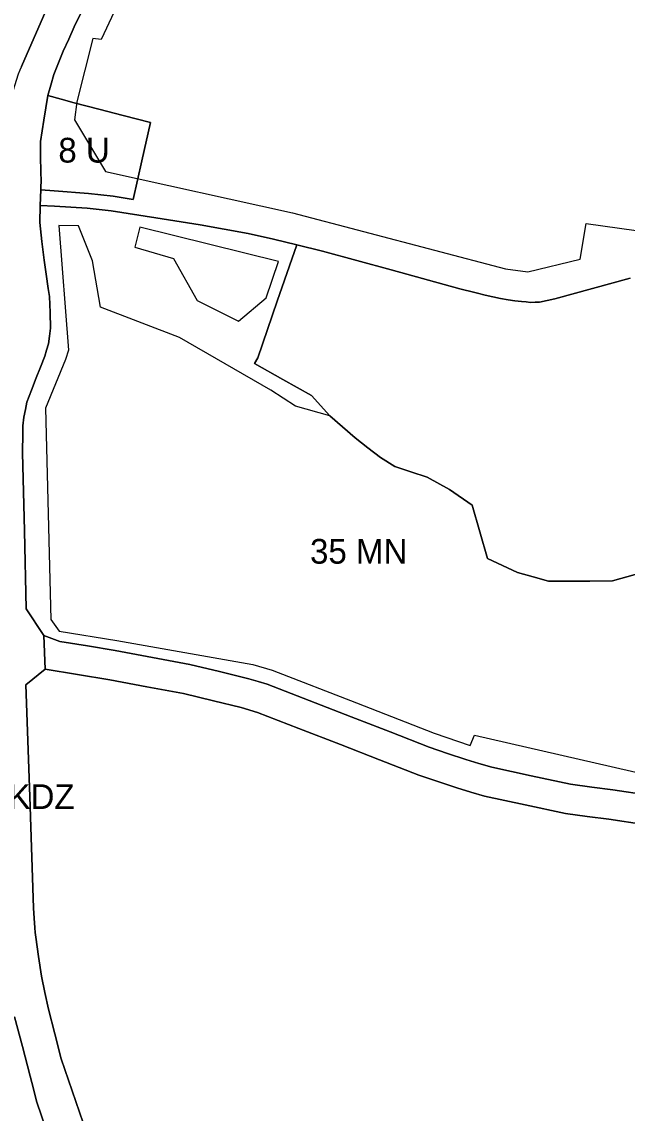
# Model space of a CAD drawing. Extents: x -294445 to -292055, y 21869 to 23693.
# Drawn here: x -293575 to -293330.1, y 22598.3 to 23039.5 of the extents above; entities that cross this region are included whole.
import ezdxf

# ---------------------------------------------------------------- set-up
doc = ezdxf.new("R2010")
doc.units = 0
for name, color, linetype in [('linie_rozgraniczajace', 7, 'Continuous'), ('linie_zabudowy_nieprzekraczalne', 7, 'Continuous'), ('oznaczenia_przeznaczen', 7, 'Continuous')]:
    doc.layers.add(name, color=color, linetype=linetype)

msp = doc.modelspace()

# ---------------------------------------------------------------- linework, layer by layer
at = {"layer": 'linie_rozgraniczajace'}
for points in [[(-293598.18, 23056.18), (-293594.8, 23074.713), (-293589.79, 23085.71), (-293551.776, 23075.056), (-293563.422, 23048.255), (-293575.068, 23021.454), (-293575.727, 23019.979), (-293576.434, 23018.253), (-293578.598, 23011.442), (-293580.762, 23004.631), (-293592.68, 23009.07)], [(-293567.426, 22991.126), (-293566.733, 22995.416), (-293566.039, 22999.706), (-293565.226, 23004.706), (-293564.413, 23009.705), (-293559.112, 23008.208), (-293553.81, 23006.71), (-293543.87, 23004.15), (-293533.93, 23001.59), (-293522.927, 22998.822), (-293526.415, 22983.261), (-293529.902, 22967.7), (-293538.002, 22968.955), (-293548.059, 22970.061), (-293561.867, 22971.094), (-293567.276, 22971.479), (-293567.12, 22976.301), (-293567.209, 22977.594), (-293567.298, 22978.886), (-293567.362, 22985.006)]]:
    msp.add_lwpolyline(points, close=True, dxfattribs=at)
for points in [[(-293575.068, 23021.454), (-293563.422, 23048.255)], [(-293551.136, 23042.939), (-293553.755, 23037.405), (-293555.994, 23032.499), (-293558.234, 23027.592), (-293560.101, 23022.855), (-293561.968, 23018.117), (-293563.19, 23013.911), (-293564.413, 23009.705), (-293565.226, 23004.706), (-293566.039, 22999.706), (-293566.733, 22995.416), (-293567.426, 22991.126), (-293567.362, 22985.006), (-293567.298, 22978.886), (-293567.209, 22977.594), (-293567.12, 22976.301), (-293567.276, 22971.479), (-293567.476, 22965.273), (-293567.702, 22958.276), (-293566.811, 22950.599), (-293565.94, 22943.17), (-293565.102, 22937.409), (-293564.264, 22931.648), (-293563.793, 22928.413), (-293563.556, 22921.992), (-293563.32, 22915.571), (-293563.761, 22912.432), (-293564.202, 22909.293), (-293564.946, 22906.779), (-293565.69, 22904.265), (-293567.391, 22899.898), (-293569.093, 22895.532), (-293570.995, 22890.613), (-293572.898, 22885.695), (-293573.505, 22882.748), (-293574.135, 22879.675), (-293574.614, 22876.19), (-293574.596, 22873.354), (-293574.578, 22870.518), (-293574.621, 22867.876), (-293574.664, 22865.234), (-293573.943, 22833.709), (-293573.222, 22802.185), (-293566.058, 22791.341), (-293565.492, 22777.838), (-293573.29, 22771.4), (-293571.766, 22726.259), (-293570.243, 22681.117), (-293569.983, 22677.189), (-293569.723, 22673.26), (-293569.542, 22671.35), (-293569.36, 22669.44), (-293568.156, 22661.578), (-293566.952, 22653.716), (-293565.59, 22647.051), (-293564.229, 22640.385), (-293561.607, 22630.327), (-293558.985, 22620.268), (-293548.673, 22590.091)], [(-293567.476, 22965.273), (-293567.276, 22971.479), (-293561.867, 22971.094), (-293548.059, 22970.061), (-293538.002, 22968.955), (-293529.902, 22967.7), (-293526.415, 22983.261), (-293522.927, 22998.822), (-293533.93, 23001.59), (-293543.87, 23004.15), (-293553.81, 23006.71), (-293559.112, 23008.208), (-293564.413, 23009.705), (-293563.19, 23013.911), (-293561.968, 23018.117), (-293560.101, 23022.855), (-293558.234, 23027.592), (-293555.994, 23032.499), (-293553.755, 23037.405), (-293551.136, 23042.939)], [(-293574.664, 22865.234), (-293574.621, 22867.876), (-293574.578, 22870.518), (-293574.596, 22873.354), (-293574.614, 22876.19), (-293574.135, 22879.675), (-293573.505, 22882.748), (-293572.898, 22885.695), (-293570.995, 22890.613), (-293569.093, 22895.532), (-293567.391, 22899.898), (-293565.69, 22904.265), (-293564.946, 22906.779), (-293564.202, 22909.293), (-293563.761, 22912.432), (-293563.32, 22915.571), (-293563.556, 22921.992), (-293563.793, 22928.413), (-293564.264, 22931.648), (-293565.102, 22937.409), (-293565.94, 22943.17), (-293566.811, 22950.599), (-293567.702, 22958.276), (-293567.476, 22965.273), (-293561.684, 22964.9), (-293548.576, 22964.082), (-293538.789, 22963.005), (-293520.8, 22960.218), (-293502.81, 22957.43), (-293483.37, 22953.85), (-293473.13, 22951.647), (-293463.772, 22949.32), (-293471.671, 22926.48), (-293479.57, 22903.64), (-293480.89, 22901.32), (-293469.335, 22894.84), (-293457.778, 22888.362), (-293450.38, 22880.16), (-293445.23, 22875.71), (-293440.08, 22871.26), (-293435.01, 22867.315), (-293429.94, 22863.37), (-293424.05, 22859.76), (-293417.565, 22857.56), (-293411.08, 22855.36), (-293401.95, 22850.45), (-293392.8, 22844.05), (-293386.57, 22822.54), (-293380.53, 22819.69), (-293374.49, 22816.84), (-293368.21, 22815.11), (-293361.93, 22813.38), (-293353.545, 22813.4), (-293345.16, 22813.42), (-293336.05, 22813.51), (-293326.93, 22816.11)], [(-293328.905, 22935.847), (-293344.144, 22931.667), (-293359.383, 22927.487), (-293362.471, 22926.836), (-293365.559, 22926.185), (-293367.365, 22926.105), (-293369.171, 22926.025), (-293370.996, 22926.225), (-293372.822, 22926.425), (-293375.557, 22926.734), (-293378.292, 22927.044), (-293381.345, 22927.647), (-293384.398, 22928.249), (-293387.536, 22929.005), (-293390.675, 22929.761), (-293393.404, 22930.442), (-293396.133, 22931.124), (-293397.784, 22931.56), (-293425.592, 22939.15), (-293453.399, 22946.741), (-293463.772, 22949.32), (-293473.13, 22951.647), (-293483.37, 22953.85), (-293502.81, 22957.43), (-293520.8, 22960.218), (-293538.789, 22963.005), (-293548.576, 22964.082), (-293561.684, 22964.9), (-293567.476, 22965.273)], [(-293326.93, 22816.11), (-293336.05, 22813.51), (-293345.16, 22813.42), (-293353.545, 22813.4), (-293361.93, 22813.38), (-293368.21, 22815.11), (-293374.49, 22816.84), (-293380.53, 22819.69), (-293386.57, 22822.54), (-293392.8, 22844.05), (-293401.95, 22850.45), (-293411.08, 22855.36), (-293417.565, 22857.56), (-293424.05, 22859.76), (-293429.94, 22863.37), (-293435.01, 22867.315), (-293440.08, 22871.26), (-293445.23, 22875.71), (-293450.38, 22880.16), (-293457.778, 22888.362), (-293469.335, 22894.84), (-293480.89, 22901.32), (-293479.57, 22903.64), (-293471.671, 22926.48), (-293463.772, 22949.32), (-293453.399, 22946.741), (-293425.592, 22939.15), (-293397.784, 22931.56), (-293396.133, 22931.124), (-293393.404, 22930.442), (-293390.675, 22929.761), (-293387.536, 22929.005), (-293384.398, 22928.249), (-293381.345, 22927.647), (-293378.292, 22927.044), (-293375.557, 22926.734), (-293372.822, 22926.425), (-293370.996, 22926.225), (-293369.171, 22926.025), (-293367.365, 22926.105), (-293365.559, 22926.185), (-293362.471, 22926.836), (-293359.383, 22927.487), (-293344.144, 22931.667), (-293328.905, 22935.847)], [(-293344.435, 22730.109), (-293353.004, 22731.225), (-293368.942, 22734.682), (-293384.88, 22738.14), (-293390.13, 22739.668), (-293395.38, 22741.197), (-293402.795, 22743.713), (-293410.21, 22746.23), (-293426, 22752.395), (-293441.79, 22758.56), (-293458.736, 22765.111), (-293475.681, 22771.662), (-293479.406, 22772.796), (-293483.13, 22773.93), (-293495.07, 22776.78), (-293507.01, 22779.63), (-293522.115, 22782.475), (-293537.219, 22785.32), (-293548.385, 22787.164), (-293559.551, 22789.008), (-293566.058, 22791.341), (-293573.222, 22802.185), (-293573.943, 22833.709), (-293574.664, 22865.234)], [(-293566.058, 22791.341), (-293559.551, 22789.008), (-293548.385, 22787.164), (-293537.219, 22785.32), (-293522.115, 22782.475), (-293507.01, 22779.63), (-293495.07, 22776.78), (-293483.13, 22773.93), (-293479.406, 22772.796), (-293475.681, 22771.662), (-293458.736, 22765.111), (-293441.79, 22758.56), (-293426, 22752.395), (-293410.21, 22746.23), (-293402.795, 22743.713), (-293395.38, 22741.197), (-293390.13, 22739.668), (-293384.88, 22738.14), (-293368.942, 22734.682), (-293353.004, 22731.225), (-293344.435, 22730.109), (-293335.867, 22728.994), (-293321.52, 22726.874)], [(-293323.368, 22715.017), (-293337.519, 22717.108), (-293346.286, 22718.249), (-293355.054, 22719.391), (-293371.443, 22722.946), (-293387.833, 22726.501), (-293393.41, 22728.125), (-293398.987, 22729.749), (-293406.655, 22732.351), (-293414.323, 22734.953), (-293430.229, 22741.164), (-293446.136, 22747.374), (-293462.867, 22753.842), (-293479.598, 22760.31), (-293486.274, 22762.343), (-293497.454, 22765.012), (-293509.515, 22767.891), (-293524.412, 22770.697), (-293539.308, 22773.502), (-293552.4, 22775.67), (-293565.492, 22777.838), (-293566.058, 22791.341)], [(-293573.29, 22771.4), (-293565.492, 22777.838), (-293552.4, 22775.67), (-293539.308, 22773.502), (-293524.412, 22770.697), (-293509.515, 22767.891), (-293497.454, 22765.012), (-293486.274, 22762.343), (-293479.598, 22760.31), (-293462.867, 22753.842), (-293446.136, 22747.374), (-293430.229, 22741.164), (-293414.323, 22734.953), (-293406.655, 22732.351), (-293398.987, 22729.749), (-293393.41, 22728.125), (-293387.833, 22726.501), (-293371.443, 22722.946), (-293355.054, 22719.391), (-293346.286, 22718.249), (-293337.519, 22717.108), (-293323.368, 22715.017)], [(-293548.673, 22590.091), (-293558.985, 22620.268), (-293561.607, 22630.327), (-293564.229, 22640.385), (-293565.59, 22647.051), (-293566.952, 22653.716), (-293568.156, 22661.578), (-293569.36, 22669.44), (-293569.542, 22671.35), (-293569.723, 22673.26), (-293569.983, 22677.189), (-293570.243, 22681.117), (-293571.766, 22726.259), (-293573.29, 22771.4)], [(-293321.52, 22726.874), (-293335.867, 22728.994), (-293344.435, 22730.109)], [(-293577.87, 22637.216), (-293574.744, 22625.222), (-293571.617, 22613.228), (-293570.297, 22608.174), (-293568.976, 22603.119), (-293560.739, 22579.011), (-293552.502, 22554.903), (-293544.186, 22532.017), (-293535.87, 22509.13), (-293533.775, 22503.209), (-293532.496, 22499.067), (-293531.216, 22494.926), (-293528.188, 22483.748), (-293525.773, 22472.607), (-293525.217, 22466.971), (-293524.661, 22461.334), (-293524.437, 22456.329), (-293524.213, 22451.323), (-293524.389, 22445.81)], [(-293560.739, 22579.011), (-293568.976, 22603.119), (-293570.297, 22608.174), (-293571.617, 22613.228), (-293574.744, 22625.222), (-293577.87, 22637.216)]]:
    msp.add_lwpolyline(points, dxfattribs=at)
at = {"layer": 'linie_zabudowy_nieprzekraczalne'}
for points in [[(-293537.618, 23043.448), (-293542.873, 23032.347), (-293546.267, 23032.693), (-293552.686, 23007.058), (-293552.686, 23007.058), (-293552.686, 23007.058), (-293553.648, 22999.899), (-293541.088, 22978.892)], [(-293541.088, 22978.892), (-293465.55, 22962.26)], [(-293465.55, 22962.26), (-293379.27, 22939.592), (-293370.366, 22938.454), (-293349.174, 22943.549), (-293346.743, 22957.909), (-293326.535, 22955.071), (-293324.378, 22966.773)], [(-293450.38, 22880.16), (-293464.236, 22884.116), (-293474.202, 22890.607), (-293511.152, 22911.913), (-293543.142, 22924.162), (-293546.342, 22942.906), (-293552.099, 22956.966), (-293560.028, 22957.128), (-293556.02, 22906.714), (-293556.02, 22906.714), (-293556.02, 22906.714), (-293556.02, 22906.714), (-293556.02, 22906.714), (-293557.229, 22902.966), (-293565.34, 22883.25), (-293565.34, 22883.25), (-293565.34, 22883.25), (-293565.34, 22883.25), (-293563.218, 22797.867), (-293559.835, 22793.124), (-293536.556, 22789.324), (-293481.558, 22779.723), (-293481.558, 22779.723), (-293481.558, 22779.723), (-293473.723, 22777.337), (-293439.617, 22764.153), (-293408.154, 22751.868), (-293393.576, 22746.921), (-293391.809, 22751.051), (-293321.855, 22735.037)], [(-293471.17, 22942.553), (-293527.268, 22956.458), (-293529.27, 22948.422), (-293513.644, 22943.843), (-293504.032, 22926.745), (-293487.357, 22918.494), (-293476.11, 22927.85), (-293471.17, 22942.553)]]:
    msp.add_lwpolyline(points, dxfattribs=at)

# ---------------------------------------------------------------- texts
at = {"layer": 'oznaczenia_przeznaczen'}
for s, p in [('8 U', (-293560.19, 22982.568)), ('35 MN', (-293458.396, 22820.421)), ('1 KDZ', (-293591.501, 22721.259))]:
    msp.add_text(s, height=10, dxfattribs=at).set_placement(p)

doc.saveas('drawing.dxf')
